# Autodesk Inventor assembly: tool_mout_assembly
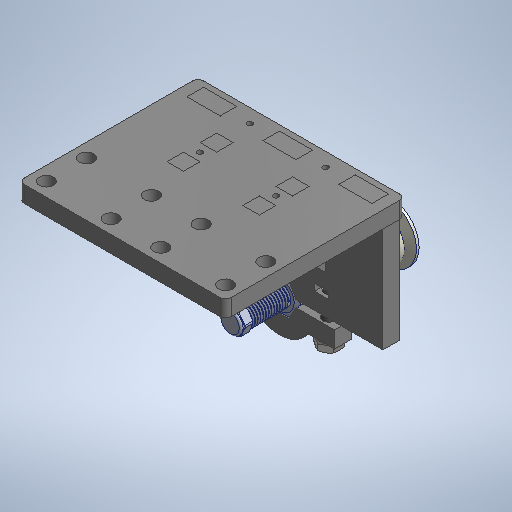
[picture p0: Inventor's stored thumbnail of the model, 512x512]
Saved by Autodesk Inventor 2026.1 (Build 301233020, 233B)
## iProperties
Created: 2026-10
Part Number: tool_mout_assembly
Document SubType Name: Assembly
Designer: hp
Author: hp
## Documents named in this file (8)
- C:\Users\hp\Documents\Inventor\DOM1_CartesianRobot\tool_mout_assembly.iam
- C:\Users\hp\Documents\Inventor\DOM1_CartesianRobot\tool_mount_part1.ipt
- C:\Users\hp\Documents\Inventor\DOM1_CartesianRobot\tool_mount_part2.ipt
- C:\Users\hp\Documents\Inventor\DOM1_CartesianRobot\tool_mount_part3.ipt
- C:\Users\hp\Documents\Inventor\DOM1_CartesianRobot\rip_5.ipt
- C:\Users\hp\Documents\Inventor\DOM1_CartesianRobot\rip_6.ipt
- C:\Users\hp\Documents\Inventor\DOM1_CartesianRobot\VACUUM NOZZLE.ipt
- C:\Users\hp\Documents\Inventor\Content Center Files\R2026\en-US\ISO 4017(1)\ISO 4017 - M4 x 16 - ISO.ipt
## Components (8 placed, 6 different names)
1. tool_mount_part1:1 — Mate:1, Mate:2, Flush:1, Mate:3, Mate:4, Flush:2, Mate:5, Mate:6, Mate:7, Flush:3
2. tool_mount_part2:1 — Mate:5, Mate:6, Mate:7, Flush:3, Flush:4, Angle:1, Mate:8, Mate:9, Flush:5
3. tool_mount_part3:1 — Flush:4, Mate:10, Mate:11, Mate:12, Mate:13, Mate:14, Mate:15
4. rip:1 — Mate:1, Mate:2, Flush:1
5. rip:2 — Mate:3, Mate:4, Flush:2
6. VACUUM NOZZLE:1 — Angle:1, Mate:8, Mate:9, Flush:5, Mate:10, Mate:11
7. ISO 4017 M4 x 16:1 — Mate:12, Mate:13
8. ISO 4017 M4 x 16:2 — Mate:14, Mate:15
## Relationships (21: Mate 15, Flush 5, Angle 1)
- Mate:1: tool_mount_part1:1 ↔ rip:1
- Mate:2: tool_mount_part1:1 ↔ rip:1
- Flush:1: tool_mount_part1:1 ↔ rip:1
- Mate:3: tool_mount_part1:1 ↔ rip:2
- Mate:4: tool_mount_part1:1 ↔ rip:2
- Flush:2: tool_mount_part1:1 ↔ rip:2
- Mate:5: tool_mount_part1:1 ↔ tool_mount_part2:1
- Mate:6: tool_mount_part1:1 ↔ tool_mount_part2:1
- Mate:7: tool_mount_part1:1 ↔ tool_mount_part2:1
- Flush:3: tool_mount_part1:1 ↔ tool_mount_part2:1
- Flush:4: tool_mount_part2:1 ↔ tool_mount_part3:1
- Angle:1: tool_mount_part2:1 ↔ VACUUM NOZZLE:1
- Mate:8: tool_mount_part2:1 ↔ VACUUM NOZZLE:1
- Mate:9: tool_mount_part2:1 ↔ VACUUM NOZZLE:1
- Flush:5: tool_mount_part2:1 ↔ VACUUM NOZZLE:1
- Mate:10: tool_mount_part3:1 ↔ VACUUM NOZZLE:1
- Mate:11: tool_mount_part3:1 ↔ VACUUM NOZZLE:1
- Mate:12: tool_mount_part3:1 ↔ ISO 4017 M4 x 16:1
- Mate:13: tool_mount_part3:1 ↔ ISO 4017 M4 x 16:1
- Mate:14: tool_mount_part3:1 ↔ ISO 4017 M4 x 16:2
- Mate:15: tool_mount_part3:1 ↔ ISO 4017 M4 x 16:2
